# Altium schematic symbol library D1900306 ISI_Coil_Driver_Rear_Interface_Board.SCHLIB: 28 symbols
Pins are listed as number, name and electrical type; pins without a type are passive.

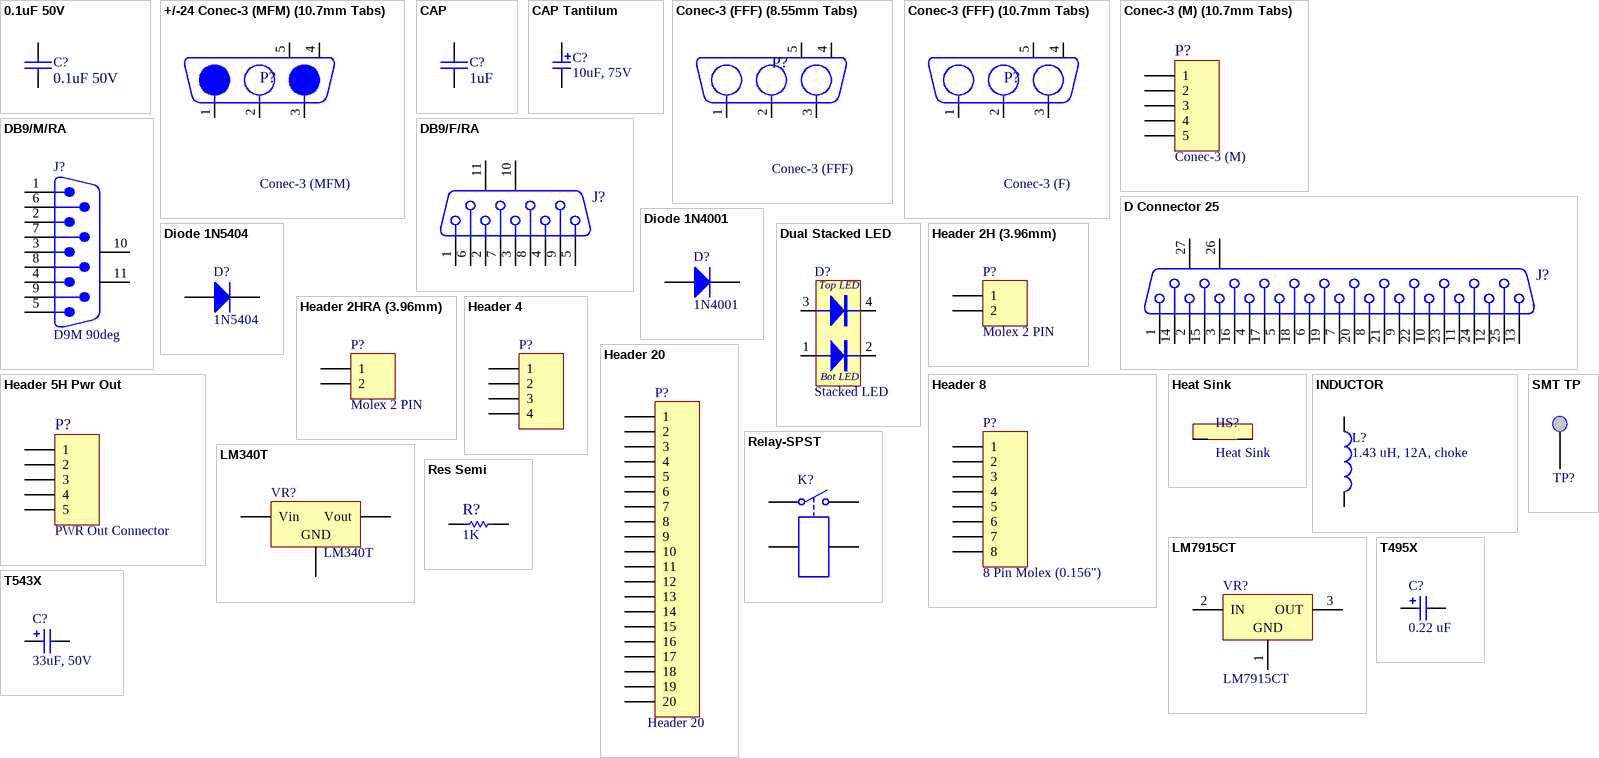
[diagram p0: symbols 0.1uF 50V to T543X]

## 0.1uF 50V
designator C?
0.1µF ±5% 50V Ceramic Capacitor X7R 1206 (3216 Metric); Manufacturer: KEMET; Manufacturer Part Number: C1206C104J5RACTU; Capacitance: 100nF
footprint 1206 (3216 Metric) CAP (Chip Capacitor; Body 3.2 x 1.6 mm (LxW typ))
pins: 1, 2

## +/-24 Conec-3 (MFM) (10.7mm Tabs)
designator P?, comment Conec-3 (MFM)
3 (Power) Position D-Sub, Combo Plug, 2 Male Pins, 1 Female Pin Connector (10.7mm Tabs) / Connec PN 303W3CPXX56K40X
footprint Conec-3 - (+/-24V M/F/M) PWR IN (10.7mm Tab)
pins: 1, 2, 3, 4, 5

## CAP
designator C?, comment 1uF
1µF ±10% 25V Ceramic Capacitor X7R 1206 (3216 Metric); Manufacturer: TDK-Lambda; Manufacturer Part Number: C1206C105K3RACTU
footprint 1206 (3216 Metric) CAP (Chip Capacitor; Body 3.2 x 1.6 mm (LxW typ))
pins: 1, 2

## CAP Tantilum
designator C?, comment 10uF, 75V
10µF Molded Tantalum Polymer Capacitor 75V 2917 (7343 Metric) 50 mOhm @ 100kHz; Manufacturer: KEMET; Manufacturer Part Number: T521X106M075ATE050; ESR (Equivalent Series Resistance): 50mR; Tolerance: 20%
footprint 2917 (7343 Metric)
pins: 1 "Anode", 2 "Cathode"

## Conec-3 (FFF) (8.55mm Tabs)
designator P?, comment Conec-3 (FFF)
3 (Power) Position D-Sub, Combo Receptacle, Female Sockets Connector; Manufacturer: Conec; Manufacturer Part Number: 3003W3SXX56N40X; Plating: Tin; Current Rating: 20A; Connector Type: D-Sub,Receptacle,Power; Number of Positions: 3
signal-integrity model Connector
footprint Conec-3 - (F) PWR OUT (8.55mm Tabs(
pins: 1, 2, 3, 4, 5

## Conec-3 (FFF) (10.7mm Tabs)
designator P?, comment Conec-3 (F)
D-Sub Mixed Contact Connectors 3W3 M R/A .370 20 AMP POWER; Manufacturer Part Number: 3003W3SXX56K40X
footprint Conec-3 - (FFF) PWR OUT (10.7mm Tabs) (3003W3SXX56K40X)
pins: 1, 2, 3, 4, 5

## Conec-3 (M) (10.7mm Tabs)
designator P?, comment Conec-3 (M)
3 (Power) Position D-Sub, Combo Plug, Male Pins Connector; Manufacturer 1: Conec; Manufacturer Part Number 1: 3003W3PXX56K40X; Current Rating: 20A; Connector Type: D-Sub,Plug,Power
footprint Conec-3 - (M) PWR IN (10.7mm Tab)
pins: 1, 2, 3, 4, 5

## D Connector 25
designator J?  (value not drawn)
25 Position D-Sub Receptacle, Female Sockets Connector; Manufacturer: TE Connectivity; Manufacturer Part Number: 57478464; PackageDocument: U; Positions: 25; Plating: Tin; Body Material: Metal; Voltage Rating: 125V; Current Rating: 6A; Number of Ports: 1; Mating Connector Lock: Yes (With); PCB Mount Retention: With; PCB Mounting Orientation: Right Angle; Preloaded: Yes; Sealable: No (Without); Pitch: 0.109inch; PCB Thickness: 1.57mm; Contact Post Length: 0.125inch; Hole Diameter: 3.18mm; Approvals: UL,CSA
footprint DSUB1.385-2H25A (Connector; D Subminiature; 25 Position; Right Angle; Pitch 1.385 mm)
signal-integrity model Connector
pins: 1, 2, 3, 4, 5, 6, 7, 8, 9, 10, 11, 12, 13, 14, 15, 16, 17, 18, 19, 20, 21, 22, 23, 24, 25, 26 MH1, 27 MH2

## DB9/F/RA
designator J?, comment D9F 90deg  (value not drawn)
Receptacle Assembly, 9 Position, Right Angle; Manufacturer: AMP - TE CONNECTIVITY; Manufacturer Part Number: 5747844-4
signal-integrity model Connector
footprint DB9/F/RA (Amphenol part# 617-C009S-AJ120)
pins: 1, 2, 3, 4, 5, 6, 7, 8, 9, 10 MH1, 11 MH2

## DB9/M/RA
designator J?, comment D9M 90deg
9 Position D-Sub Plug, Male Pins Connector; Manufacturer: TE Connectivity; Manufacturer Part Number: 5747840-3; Plating: Tin; Body Material: Metal,Steel; Voltage Rating: 125V; Current Rating: 6A; Number of Positions: 9; Number of Ports: 1; Mating Connector Lock: Yes (With); PCB Mount Retention: With; Preloaded: Yes; Sealable: No (Without); Circuit Application: Signal; Connector System: Board-to-Board; Pitch: 0.108inch; PCB Thickness: 1.57mm; Contact Post Length: 0.125inch; Row Spacing: 2.84mm; Approvals: CSA,UL
footprint DB9/M/RA (Amphenol Part# 617-C009P-AJ120)
pins: 1, 2, 3, 4, 5, 6, 7, 8, 9, 10 MH1, 11 MH2

## Diode 1N4001
designator D?, comment 1N4001
1 Amp General Purpose Rectifier; Manufacturer: Diodes; Manufacturer Part Number: 1N4001G-T; Max Surge Current: 30A; Recovery Time: 2us; Forward Voltage: 1V; Peak Reverse Current: 5uA; Reverse Voltage (DC): 50V; Average Rectified Current: 1A; Element Configuration: Single; Polarity: Standard; Capacitance: 8pF
footprint DO-41 (Diode, Axial; Body 5.2 x 2.7 mm (LxDia. max), Lead Dia. 0.86 mm (max))
simulation model 1N4001 (DIODE)
signal-integrity model 1N4001
pins: 1 A, 2 K

## Diode 1N5404
designator D?, comment 1N5404
Diode Standard 400V 3A Through Hole DO-201AD; Manufacturer: Vishay Semiconductors; Manufacturer Part Number: 1N5404-E3/54; Peak Reverse Current: 5uA; Max Surge Current: 200A; Forward Voltage: 1.2V; Element Configuration: Single; Capacitance: 30pF
simulation model 1N4001 (DIODE)
signal-integrity model 1N4001
footprint DO-201AD (Diode Standard 400V 3A Through Hole DO-201AD)
pins: 1 A, 2 K

## Dual Stacked LED
designator D?, comment Stacked LED
Dual Green LED; Manufacturer: Lumex; Manufacturer Part Number: SSF-LXH240GGD; Voltage Rating: 2.2V; Number of Contacts: 2; Viewing Angle: 60°; Lens Style: Diffused,Tinted,Round,Colored; Luminous Intensity: 40mcd; Forward Current: 25mA; Wavelength: 565nm
footprint DUAL_LED (Stacked LED GREEN, Digi Key Part # 67-1321-ND)
pins: 1 COM, 2 CATHODE, 3 ANODE, 4 ANODE

## Header 2H (3.96mm)
designator P?, comment Molex 2 PIN
Connector Header Through Hole 2 position 0.156" (3.96mm); Number of Positions: 2; Gender: Male; Contact Resistance: 6mR; Current Rating: 7A; Voltage Rating: 250V; Insulation Resistance: 50GR; Glow Wire Compliant: Non-compliant
signal-integrity model Connector
footprint MOLE_2PIN_0.156
pins: 1, 2

## Header 2HRA (3.96mm)
designator P?, comment Molex 2 PIN
Connector Header Through Hole, Right Angle 2 position 0.156" (3.96mm); Number of Positions: 2; Gender: Male; Current Rating: 7A; Voltage Rating: 250V; Contact Resistance: 10mR; Insulation Resistance: 50GR; Glow Wire Compliant: Non-compliant
signal-integrity model Connector
footprint MOLE_2PIN_0.156RA
pins: 1, 2

## Header 4
designator P?  (value not drawn)
Header, 4-Pin; Manufacturer: Molex; Number of Positions: 4; Gender: Male; Contact Resistance: 6mR; Voltage Rating: 250V; Current Rating: 7A; Insulation Resistance: 50GR; Pitch: 3.96mm; Approvals: UL,CSA,TUV; Glow Wire Compliant: Non-compliant
footprint 4 PIN_MOLEX
signal-integrity model Connector
pins: 1, 2, 3, 4

## Header 5H Pwr Out
designator P?, comment PWR Out Connector
3 (Power) Position D-Sub, Combo Receptacle, Female Sockets Connector; Manufacturer: Conec; Manufacturer Part Number: 3003W3SXX56N40X; Plating: Tin; Connector Type: D-Sub,Receptacle,Power; Number of Positions: 3; Current Rating: 20A
signal-integrity model Connector
footprint DBPWR_CON - PWR OUT
pins: 1, 2, 3, 4, 5

## Header 8
designator P?, comment 8 Pin Molex (0.156")
Connector Header Through Hole 8 position 0.156" (3.96mm); Number of Positions: 8; Gender: Male; Connector Type: Male Pin; Contact Resistance: 6mR; Max Voltage Rating (AC): 250V
footprint 8 pin_Molex(0.156)
signal-integrity model Connector
pins: 1, 2, 3, 4, 5, 6, 7, 8

## Header 20
designator P?
Header, 20-Pin; Manufacturer: Amphenol FCI; Manufacturer Part Number: 71918-120LF; Mating Cycles: 250; Number of Poles: 20; Max Voltage Rating (AC): 1.5kV; Insulation Resistance: 100GR; Gender: Male; Connector Type: Male Pin; Current Rating: 1A; Pitch: 2.54mm; Row Spacing: 0.1inch; Hole Diameter: 1mm; Contact Post Length: 2.9mm; Approvals: UL,CSA
footprint IDC 20 _Vertical
signal-integrity model Connector
pins: 1, 2, 3, 4, 5, 6, 7, 8, 9, 10, 11, 12, 13, 14, 15, 16, 17, 18, 19, 20

## Heat Sink
designator HS?
Heat Sink TO-220 Aluminum 8.0W @ 80°C Board Level, Vertical; Manufacturer: Ohmite; Manufacturer Part Number: EA-T220-38E; Shape: Fins,Rectangular; Thermal Resistance @ Forced Air Flow (100 LFM): 4°C/W; Natural Thermal Resistance: 10.4°C/W
footprint Heat SInk TO-220
pins: 1 GND, 2 GND

## INDUCTOR
designator L?, comment 1.43 uH, 12A, choke
1mH Shielded  Inductor 550mA 1.82Ohm Max Nonstandard; Manufacturer: Sumida; Manufacturer Part Number: CDRH127NP-102MC; Core Material: Ferrite; Tolerance: 20%; DC Resistance (DCR): 1.82R; Test Frequency: 1kHz
footprint Power choke (PCD1572-ND)
pins: 1, 2

## LM340T
designator VR?
Linear Voltage Regulator IC Positive Fixed 1 Output  1.5A TO-220-3; Manufacturer: TI National Semiconductor; Manufacturer Part Number: LM340T-15/NOPB; Dropout Voltage: 2V; Number of Outputs: 1; Output Current: 1A; Max Input Voltage: 35V; Output Voltage: 15V; Max Supply Voltage: 30V; Min Supply Voltage: 17.5V; Min Input Voltage: 17.7V; Quiescent Current: 8mA; Accuracy: 2%; Tolerance: 5%; Power Supply Rejection Ratio (PSRR): 80dB
footprint TO-220AB (TO, Thru-Hole, Vertical, Heatsink Mounted; 3 In-Line Leads; Pitch 2.54 mm)
pins: 1 Vin, 2 GND, 3 Vout

## LM7915CT
designator VR?
Linear Voltage Regulator IC Negative Fixed 1 Output  1.5A TO-220-3; Manufacturer: TI National Semiconductor; Manufacturer Part Number: LM7915CT/NOPB; Number of Outputs: 1; Output Voltage: -15V; Max Input Voltage: -23V; Min Input Voltage: -17.5V; Dropout Voltage: 1.1V; Quiescent Current: 3mA; Accuracy: 4%; Min Output Voltage: -14.4V; Max Output Voltage: -15.6V; Tolerance: 5%; Power Supply Rejection Ratio (PSRR): 70dB
footprint TO-220AB (TO, Thru-Hole, Vertical, Heatsink Mounted; 3 In-Line Leads; Pitch 2.54 mm)
pins: 1 GND (power), 2 IN (power), 3 OUT (power)

## Relay-SPST
designator K?  (value not drawn)
Single-Pole Single-Throw Relay; Manufacturer: Panasonic; Manufacturer Part Number: JQ1A-24V-F; Voltage Rating (AC): 250V; Power Rating: 200mW; Max Voltage Rating (DC): 110V; Contact Current Rating: 5A; Throw Configuration: SPST; Coil Resistance: 2.88kR; Coil Current: 8.3mA; Operate Time: 20ms; Release Time: 10ms; Coil Voltage (DC): 24V; Coil Type: Non-Latching; Relay Type: General Purpose
footprint Panasonic Relay_5A
simulation model SPSTRELAY (Spice Subcircuit)
pins: 1, 2, 3, 4

## Res Semi
designator R?, comment 1K
1 kOhms ±0.5% 0.25W, 1/4W Chip Resistor 1206 (3216 Metric)  Thin Film; Manufacturer: Yageo; Manufacturer Part Number: RT1206DRE071KL; Resistance: 1kR; Max Power Dissipation: 250mW; Temperature Coefficient: 50ppm/°C; Voltage Rating (DC): 200V
footprint 3216[1206] (Chip Resistor; Body 3.2 x 1.6 mm (LxW typ))
simulation model RES (Semiconductor Resistor)
signal-integrity model Res Semi
pins: 1, 2

## SMT TP
designator TP?  (value not drawn)
PC Test Point, Miniature Phosphor Bronze, Silver Plating Surface Mount Mounting Type; Manufacturer: Keystone Electronics; Manufacturer Part Number: 5019
footprint SMT_TP (Surface Mount Test Point)
pins: 1

## T495X
designator C?, comment 0.22 uF
0.22µF Molded Tantalum Capacitors 50V 1206 (3216 Metric) 18Ohm; Manufacturer: Kyocera AVX; Manufacturer Part Number: TAJA224K050RNJ; Capacitance: 220nF; Tolerance: 10%; ESR (Equivalent Series Resistance): 18R; Leakage Current: 500nA; Polarity: Polar; Dissipation Factor: 4%; Voltage: 35V
footprint T491X
simulation model CAP (Capacitor)
signal-integrity model T495X
pins: 1, 2

## T543X
designator C?, comment 33uF, 50V
33µF Molded Tantalum Polymer Capacitor 50V 2917 (7343 Metric) 40mOhm @ 100kHz; Manufacturer: KEMET; Manufacturer Part Number: T543X336M050AHE040; Tolerance: 20%; ESR (Equivalent Series Resistance): 40mR; Leakage Current: 165uA; Polarity: Polar; Dissipation Factor: 10%
simulation model CAP (Capacitor)
signal-integrity model T495X
footprint T543x
pins: 1, 2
